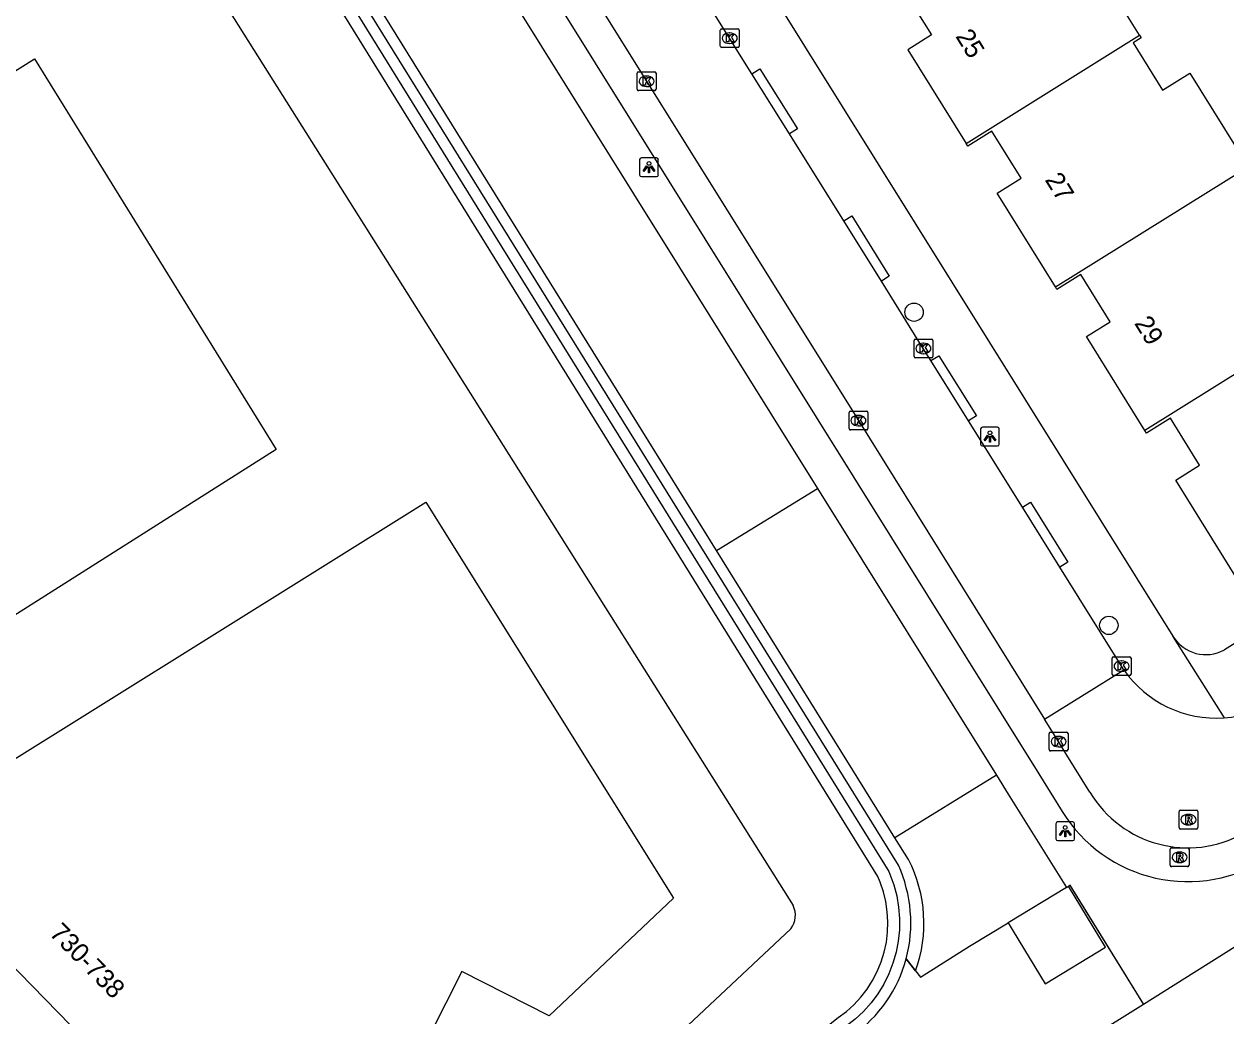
# Model space of a CAD drawing. Extents: x 158838 to 160074, y 386376 to 387776.
# Drawn here: x 159064.3 to 159128.3, y 386920.8 to 386973.6 of the extents above; entities that cross this region are included whole.
import ezdxf

# ---------------------------------------------------------------- set-up
doc = ezdxf.new("R2010")
doc.units = 0
for name, color, linetype in [('IMGEO_Boom', 7, 'Continuous'), ('IMGEO_Groenvoorziening', 7, 'Continuous'), ('IMGEO_Hek', 7, 'Continuous'), ('IMGEO_Kolk', 7, 'Continuous'), ('IMGEO_Lichtpunt', 7, 'Continuous'), ('IMGEO_Loofbos', 7, 'Continuous'), ('IMGEO_Muur', 7, 'Continuous'), ('IMGEO_Pand', 7, 'Continuous'), ('IMGEO_Pand_nummerreeks', 7, 'Continuous'), ('IMGEO_Rijbaan_lokaal_gesloten', 7, 'Continuous'), ('IMGEO_Rioolput', 7, 'Continuous'), ('IMGEO_Voetpad_open', 7, 'Continuous')]:
    doc.layers.add(name, color=color, linetype=linetype)

msp = doc.modelspace()

# ---------------------------------------------------------------- linework, layer by layer
at = {"layer": 'IMGEO_Boom'}
for centre in [(159111.716, 386958.243), (159122.083, 386941.572)]:
    msp.add_circle(centre, 0.489, dxfattribs=at)
at = {"layer": 'IMGEO_Groenvoorziening'}
for points in [[(159110.881, 386928.808), (159066.743, 387000), (159047.544, 387030.967)], [(159047.042, 387030.681), (159066.053, 387000), (159110.378, 386928.464), (159110.435, 386928.33), (159110.64, 386927.76), (159110.794, 386927.173), (159110.895, 386926.575), (159110.942, 386925.971), (159110.935, 386925.364), (159110.873, 386924.761), (159110.758, 386924.166), (159110.591, 386923.583), (159110.372, 386923.018), (159110.103, 386922.474), (159109.787, 386921.957), (159109.426, 386921.47), (159109.022, 386921.017), (159108.58, 386920.602), (159108.103, 386920.228), (159104.096, 386917.095), (159102.915, 386915.575)], [(159101.209, 386945.557), (159067.427, 387000), (159057.059, 387016.709)], [(159101.209, 386945.557), (159106.574, 386948.859)], [(159110.699, 386930.263), (159101.209, 386945.557)], [(159116.105, 386933.589), (159110.699, 386930.263)], [(159111.422, 386929.098), (159110.699, 386930.263)], [(159111.801, 386923.181), (159112.065, 386922.841), (159114.673, 386924.489), (159116.716, 386925.733)], [(159111.302, 386923.823), (159111.801, 386923.181)]]:
    msp.add_lwpolyline(points, dxfattribs=at)
for centre, radius, start, end in [((159104.809, 386925.704), 7.433, 340.1599, 27.16999), ((159104.003, 386925.717), 7.54, 345.4536, 24.20113), ((159104.188, 386925.752), 7.371, 305.33412, 344.82886)]:
    msp.add_arc(centre, radius, start, end, dxfattribs=at)
at = {"layer": 'IMGEO_Hek'}
msp.add_lwpolyline([(159111.801, 386923.181), (159111.302, 386923.823)], dxfattribs=at)
at = {"layer": 'IMGEO_Kolk'}
for p, q in [((159101.404, 386972.403), (159101.404, 386973.255)), ((159101.479, 386973.329), (159102.331, 386973.329)), ((159102.405, 386973.255), (159102.405, 386972.403)), ((159101.915, 386972.549), (159101.89, 386972.549)), ((159101.892, 386973.109), (159101.917, 386973.109)), ((159102.331, 386972.329), (159101.479, 386972.329)), ((159096.98, 386970.111), (159096.98, 386970.963)), ((159097.055, 386971.037), (159097.907, 386971.037)), ((159097.468, 386970.817), (159097.493, 386970.817)), ((159097.981, 386970.963), (159097.981, 386970.111)), ((159097.907, 386970.037), (159097.055, 386970.037)), ((159097.491, 386970.257), (159097.466, 386970.257)), ((159111.713, 386955.889), (159111.713, 386956.741)), ((159111.788, 386956.815), (159112.64, 386956.815)), ((159112.201, 386956.595), (159112.226, 386956.595)), ((159112.714, 386956.741), (159112.714, 386955.889)), ((159112.224, 386956.035), (159112.199, 386956.035)), ((159112.64, 386955.815), (159111.788, 386955.815)), ((159108.253, 386952.046), (159108.253, 386952.898)), ((159108.328, 386952.972), (159109.18, 386952.972)), ((159108.741, 386952.752), (159108.766, 386952.752)), ((159109.254, 386952.898), (159109.254, 386952.046)), ((159108.764, 386952.192), (159108.739, 386952.192)), ((159109.18, 386951.972), (159108.328, 386951.972)), ((159122.337, 386939.896), (159123.189, 386939.896)), ((159122.262, 386938.97), (159122.262, 386939.822)), ((159122.75, 386939.676), (159122.775, 386939.676)), ((159123.263, 386939.822), (159123.263, 386938.97)), ((159123.189, 386938.896), (159122.337, 386938.896)), ((159122.773, 386939.116), (159122.748, 386939.116)), ((159118.91, 386934.957), (159118.91, 386935.809)), ((159118.985, 386935.883), (159119.837, 386935.883)), ((159119.398, 386935.663), (159119.423, 386935.663)), ((159119.911, 386935.809), (159119.911, 386934.957)), ((159119.837, 386934.883), (159118.985, 386934.883)), ((159119.421, 386935.103), (159119.396, 386935.103))]:
    msp.add_line(p, q, dxfattribs=at)
for points in [[(159101.404, 386972.403), (159101.404, 386973.255)], [(159101.479, 386973.329), (159102.331, 386973.329)], [(159102.405, 386973.255), (159102.405, 386972.403)], [(159101.725, 386973.029), (159101.848, 386973.029), (159101.848, 386972.878), (159101.978, 386973.029), (159102.142, 386973.029), (159101.996, 386972.878), (159102.149, 386972.629), (159101.997, 386972.629), (159101.912, 386972.793), (159101.848, 386972.726), (159101.848, 386972.629), (159101.725, 386972.629), (159101.725, 386973.029)], [(159102.331, 386972.329), (159101.479, 386972.329)], [(159096.98, 386970.111), (159096.98, 386970.963)], [(159097.055, 386971.037), (159097.907, 386971.037)], [(159097.301, 386970.737), (159097.424, 386970.737), (159097.424, 386970.586), (159097.554, 386970.737), (159097.718, 386970.737), (159097.572, 386970.586), (159097.725, 386970.337), (159097.573, 386970.337), (159097.488, 386970.501), (159097.424, 386970.434), (159097.424, 386970.337), (159097.301, 386970.337), (159097.301, 386970.737)], [(159097.981, 386970.963), (159097.981, 386970.111)], [(159097.907, 386970.037), (159097.055, 386970.037)], [(159111.713, 386955.889), (159111.713, 386956.741)], [(159111.788, 386956.815), (159112.64, 386956.815)], [(159112.034, 386956.515), (159112.157, 386956.515), (159112.157, 386956.364), (159112.287, 386956.515), (159112.451, 386956.515), (159112.305, 386956.364), (159112.458, 386956.115), (159112.306, 386956.115), (159112.221, 386956.279), (159112.157, 386956.212), (159112.157, 386956.115), (159112.034, 386956.115), (159112.034, 386956.515)], [(159112.714, 386956.741), (159112.714, 386955.889)], [(159112.64, 386955.815), (159111.788, 386955.815)], [(159108.253, 386952.046), (159108.253, 386952.898)], [(159108.328, 386952.972), (159109.18, 386952.972)], [(159108.574, 386952.672), (159108.697, 386952.672), (159108.697, 386952.521), (159108.827, 386952.672), (159108.991, 386952.672), (159108.845, 386952.521), (159108.998, 386952.272), (159108.846, 386952.272), (159108.761, 386952.436), (159108.697, 386952.369), (159108.697, 386952.272), (159108.574, 386952.272), (159108.574, 386952.672)], [(159109.254, 386952.898), (159109.254, 386952.046)], [(159109.18, 386951.972), (159108.328, 386951.972)], [(159122.337, 386939.896), (159123.189, 386939.896)], [(159122.262, 386938.97), (159122.262, 386939.822)], [(159122.583, 386939.596), (159122.706, 386939.596), (159122.706, 386939.445), (159122.836, 386939.596), (159123, 386939.596), (159122.854, 386939.445), (159123.007, 386939.196), (159122.855, 386939.196), (159122.77, 386939.36), (159122.706, 386939.293), (159122.706, 386939.196), (159122.583, 386939.196), (159122.583, 386939.596)], [(159123.263, 386939.822), (159123.263, 386938.97)], [(159123.189, 386938.896), (159122.337, 386938.896)], [(159118.91, 386934.957), (159118.91, 386935.809)], [(159118.985, 386935.883), (159119.837, 386935.883)], [(159119.231, 386935.583), (159119.354, 386935.583), (159119.354, 386935.432), (159119.484, 386935.583), (159119.648, 386935.583), (159119.502, 386935.432), (159119.655, 386935.183), (159119.503, 386935.183), (159119.418, 386935.347), (159119.354, 386935.28), (159119.354, 386935.183), (159119.231, 386935.183), (159119.231, 386935.583)], [(159119.911, 386935.809), (159119.911, 386934.957)], [(159119.837, 386934.883), (159118.985, 386934.883)]]:
    msp.add_lwpolyline(points, dxfattribs=at)
for centre, start, end in [((159101.481, 386973.253), 91.55205, 178.44795), ((159101.481, 386973.253), 91.55205, 178.44795), ((159102.329, 386973.253), 1.55205, 88.44795), ((159102.329, 386973.253), 1.55205, 88.44795), ((159101.481, 386972.405), 181.55205, 268.44795), ((159101.481, 386972.405), 181.55205, 268.44795), ((159102.329, 386972.405), 271.55205, 358.44795), ((159102.329, 386972.405), 271.55205, 358.44795), ((159097.057, 386970.961), 91.55205, 178.44795), ((159097.057, 386970.961), 91.55205, 178.44795), ((159097.905, 386970.961), 1.55205, 88.44795), ((159097.905, 386970.961), 1.55205, 88.44795), ((159097.057, 386970.113), 181.55205, 268.44795), ((159097.057, 386970.113), 181.55205, 268.44795), ((159097.905, 386970.113), 271.55205, 358.44795), ((159097.905, 386970.113), 271.55205, 358.44795), ((159111.79, 386956.739), 91.55205, 178.44795), ((159111.79, 386956.739), 91.55205, 178.44795), ((159112.638, 386956.739), 1.55205, 88.44795), ((159112.638, 386956.739), 1.55205, 88.44795), ((159111.79, 386955.891), 181.55205, 268.44795), ((159111.79, 386955.891), 181.55205, 268.44795), ((159112.638, 386955.891), 271.55205, 358.44795), ((159112.638, 386955.891), 271.55205, 358.44795), ((159108.33, 386952.896), 91.55205, 178.44795), ((159108.33, 386952.896), 91.55205, 178.44795), ((159109.178, 386952.896), 1.55205, 88.44795), ((159109.178, 386952.896), 1.55205, 88.44795), ((159108.33, 386952.048), 181.55205, 268.44795), ((159108.33, 386952.048), 181.55205, 268.44795), ((159109.178, 386952.048), 271.55205, 358.44795), ((159109.178, 386952.048), 271.55205, 358.44795), ((159122.339, 386939.82), 91.55205, 178.44795), ((159122.339, 386939.82), 91.55205, 178.44795), ((159123.187, 386939.82), 1.55205, 88.44795), ((159123.187, 386939.82), 1.55205, 88.44795), ((159122.339, 386938.972), 181.55205, 268.44795), ((159122.339, 386938.972), 181.55205, 268.44795), ((159123.187, 386938.972), 271.55205, 358.44795), ((159123.187, 386938.972), 271.55205, 358.44795), ((159118.987, 386935.807), 91.55205, 178.44795), ((159118.987, 386935.807), 91.55205, 178.44795), ((159119.835, 386935.807), 1.55205, 88.44795), ((159119.835, 386935.807), 1.55205, 88.44795), ((159118.987, 386934.959), 181.55205, 268.44795), ((159118.987, 386934.959), 181.55205, 268.44795), ((159119.835, 386934.959), 271.55205, 358.44795), ((159119.835, 386934.959), 271.55205, 358.44795)]:
    msp.add_arc(centre, 0.0765, start, end, dxfattribs=at)
for centre, major_axis, ratio, start_param, end_param in [((159101.891, 386972.829), (-0.387, 0.002), 0.722429, 4.712389, 7.853982), ((159101.916, 386972.829), (-0.39, 0.002), 0.717154, 1.570796, 4.712389), ((159097.467, 386970.537), (-0.387, 0.002), 0.722429, 4.712389, 7.853982), ((159097.492, 386970.537), (-0.39, 0.002), 0.717154, 1.570796, 4.712389), ((159112.2, 386956.315), (-0.387, 0.002), 0.722429, 4.712389, 7.853982), ((159112.225, 386956.315), (-0.39, 0.002), 0.717154, 1.570796, 4.712389), ((159108.74, 386952.472), (-0.387, 0.002), 0.722429, 4.712389, 7.853982), ((159108.765, 386952.472), (-0.39, 0.002), 0.717154, 1.570796, 4.712389), ((159122.749, 386939.396), (-0.387, 0.002), 0.722429, 4.712389, 7.853982), ((159122.774, 386939.396), (-0.39, 0.002), 0.717154, 1.570796, 4.712389), ((159119.397, 386935.383), (-0.387, 0.002), 0.722429, 4.712389, 7.853982), ((159119.422, 386935.383), (-0.39, 0.002), 0.717154, 1.570796, 4.712389)]:
    msp.add_ellipse(centre, major_axis=major_axis, ratio=ratio, start_param=start_param, end_param=end_param, dxfattribs=at)
at = {"layer": 'IMGEO_Lichtpunt'}
for p, q in [((159097.108, 386966.365), (159097.108, 386965.558)), ((159097.108, 386966.365), (159097.108, 386965.558)), ((159098.01, 386966.46), (159097.202, 386966.46)), ((159098.01, 386966.46), (159097.202, 386966.46)), ((159098.104, 386965.558), (159098.104, 386966.365)), ((159098.104, 386965.558), (159098.104, 386966.365)), ((159097.202, 386965.464), (159098.01, 386965.464)), ((159097.202, 386965.464), (159098.01, 386965.464)), ((159115.257, 386952.026), (159115.257, 386951.219)), ((159115.257, 386952.026), (159115.257, 386951.219)), ((159116.159, 386952.121), (159115.351, 386952.121)), ((159116.159, 386952.121), (159115.351, 386952.121)), ((159116.253, 386951.219), (159116.253, 386952.026)), ((159116.253, 386951.219), (159116.253, 386952.026)), ((159115.351, 386951.125), (159116.159, 386951.125)), ((159115.351, 386951.125), (159116.159, 386951.125)), ((159119.265, 386931.011), (159119.265, 386930.204)), ((159119.265, 386931.011), (159119.265, 386930.204)), ((159120.167, 386931.106), (159119.359, 386931.106)), ((159120.167, 386931.106), (159119.359, 386931.106)), ((159120.261, 386930.204), (159120.261, 386931.011)), ((159120.261, 386930.204), (159120.261, 386931.011)), ((159119.359, 386930.11), (159120.167, 386930.11)), ((159119.359, 386930.11), (159120.167, 386930.11))]:
    msp.add_line(p, q, dxfattribs=at)
for points in [[(159097.482, 386966.029), (159097.521, 386966.001), (159097.333, 386965.739), (159097.295, 386965.766), (159097.482, 386966.029)], [(159097.584, 386965.981), (159097.631, 386965.981), (159097.631, 386965.659), (159097.584, 386965.659), (159097.584, 386965.981)], [(159097.694, 386966.001), (159097.732, 386966.028), (159097.919, 386965.766), (159097.88, 386965.738), (159097.694, 386966.001)], [(159115.631, 386951.69), (159115.67, 386951.662), (159115.482, 386951.4), (159115.444, 386951.427), (159115.631, 386951.69)], [(159115.733, 386951.642), (159115.78, 386951.642), (159115.78, 386951.32), (159115.733, 386951.32), (159115.733, 386951.642)], [(159115.843, 386951.662), (159115.881, 386951.689), (159116.068, 386951.427), (159116.029, 386951.399), (159115.843, 386951.662)], [(159119.639, 386930.675), (159119.678, 386930.647), (159119.49, 386930.385), (159119.452, 386930.412), (159119.639, 386930.675)], [(159119.741, 386930.627), (159119.788, 386930.627), (159119.788, 386930.305), (159119.741, 386930.305), (159119.741, 386930.627)], [(159119.851, 386930.647), (159119.889, 386930.674), (159120.076, 386930.412), (159120.037, 386930.384), (159119.851, 386930.647)]]:
    msp.add_lwpolyline(points, dxfattribs=at)
for centre in [(159097.607, 386966.163), (159115.756, 386951.824), (159119.764, 386930.809)]:
    msp.add_circle(centre, 0.0994, dxfattribs=at)
for centre, start, end in [((159097.202, 386966.365), 90, 180), ((159097.202, 386966.365), 90, 180), ((159098.01, 386966.365), 0, 90), ((159098.01, 386966.365), 0, 90), ((159097.202, 386965.558), 180, 270), ((159097.202, 386965.558), 180, 270), ((159098.01, 386965.558), 270, 0), ((159098.01, 386965.558), 270, 360), ((159115.351, 386952.026), 90, 180), ((159115.351, 386952.026), 90, 180), ((159116.159, 386952.026), 0, 90), ((159116.159, 386952.026), 0, 90), ((159115.351, 386951.219), 180, 270), ((159115.351, 386951.219), 180, 270), ((159116.159, 386951.219), 270, 0), ((159116.159, 386951.219), 270, 360), ((159119.359, 386931.011), 90, 180), ((159119.359, 386931.011), 90, 180), ((159120.167, 386931.011), 0, 90), ((159120.167, 386931.011), 0, 90), ((159119.359, 386930.204), 180, 270), ((159119.359, 386930.204), 180, 270), ((159120.167, 386930.204), 270, 0), ((159120.167, 386930.204), 270, 360)]:
    msp.add_arc(centre, 0.0946, start, end, dxfattribs=at)
at = {"layer": 'IMGEO_Loofbos'}
for points in [[(159102.365, 386915.829), (159103.677, 386917.524), (159107.676, 386920.687), (159108.111, 386921.014), (159108.514, 386921.378), (159108.884, 386921.777), (159109.216, 386922.207), (159109.509, 386922.665), (159109.759, 386923.147), (159109.966, 386923.65), (159110.127, 386924.17), (159110.24, 386924.701), (159110.306, 386925.241), (159110.323, 386925.784), (159110.292, 386926.327), (159110.212, 386926.865), (159110.085, 386927.393), (159109.911, 386927.908), (159109.791, 386928.194), (159065.319, 387000), (159046.571, 387030.271)], [(159027.668, 387025.411), (159031.623, 387024.617), (159033.066, 387024.328), (159037.285, 387026.957), (159040.771, 387029.129), (159042.317, 387026.665), (159042.882, 387025.766), (159059.05, 387000), (159105.278, 386926.65)], [(159105.16, 386925.412), (159097.39, 386918.123)]]:
    msp.add_lwpolyline(points, dxfattribs=at)
msp.add_arc((159104.205, 386926.128), 1.193, 323.14737, 25.96323, dxfattribs=at)
at = {"layer": 'IMGEO_Muur'}
msp.add_lwpolyline([(159119.995, 386927.764), (159123.926, 386921.395)], dxfattribs=at)
at = {"layer": 'IMGEO_Pand'}
for points in [[(159123.72, 386972.986), (159120.607, 386977.979), (159120.174, 386977.709), (159118.609, 386980.218), (159119.042, 386980.488), (159118.957, 386980.624)], [(159109.725, 386974.863), (159109.81, 386974.727), (159111.081, 386975.519), (159112.647, 386973.003), (159111.377, 386972.212), (159114.488, 386967.227)], [(159114.488, 386967.227), (159123.72, 386972.986)], [(159123.72, 386972.986), (159123.805, 386972.85), (159123.373, 386972.58), (159124.938, 386970.071), (159126.388, 386970.975), (159129.502, 386965.983)], [(159046.555, 386960.214), (159064.894, 386971.726), (159077.764, 386950.938), (159061.799, 386940.822), (159063.111, 386938.73), (159055.719, 386934.097), (159052.509, 386939.297)], [(159119.237, 386959.595), (159116.133, 386964.584), (159117.408, 386965.377), (159115.848, 386967.884), (159114.573, 386967.091), (159114.488, 386967.227)], [(159119.237, 386959.595), (159128.476, 386965.343), (159129.502, 386965.983)], [(159124.005, 386951.946), (159120.887, 386956.943), (159122.162, 386957.736), (159120.597, 386960.252), (159119.322, 386959.459), (159119.237, 386959.595)], [(159133.243, 386957.719), (159124.005, 386951.946)], [(159136.383, 386945.364), (159134.825, 386947.869), (159128.849, 386944.162), (159125.646, 386949.307), (159126.914, 386950.096), (159125.358, 386952.599), (159124.09, 386951.81), (159124.005, 386951.946)], [(159057.026, 386930.203), (159085.733, 386948.136), (159098.905, 386927.043), (159092.293, 386920.792), (159087.651, 386923.144), (159084.236, 386916.402), (159079.601, 386918.778), (159073.847, 386913.112), (159073.617, 386913.315), (159059.33, 386927.96), (159057.958, 386926.654), (159057.813, 386926.806), (159059.214, 386928.192), (159057.381, 386930.049), (159057.194, 386929.933)], [(159116.716, 386925.733), (159116.984, 386925.293), (159118.69, 386922.482), (159121.909, 386924.436), (159119.935, 386927.687)], [(159119.83, 386927.623), (159116.716, 386925.733)], [(159119.83, 386927.623), (159119.935, 386927.687)], [(159130.533, 386925.542), (159123.926, 386921.395)], [(159123.926, 386921.395), (159112.501, 386914.25), (159114.935, 386910.349), (159122.629, 386915.15), (159125.239, 386910.966)]]:
    msp.add_lwpolyline(points, dxfattribs=at)
at = {"layer": 'IMGEO_Rijbaan_lokaal_gesloten'}
for points in [[(159052.677, 387042.36), (159054.093, 387040.05), (159064.841, 387022.833), (159075.554, 387005.639), (159079.076, 387000), (159097.478, 386970.538), (159108.751, 386952.473), (159118.667, 386936.572)], [(159103.083, 386970.938), (159101.9, 386972.828), (159100.276, 386975.439)], [(159105.081, 386967.744), (159103.083, 386970.938)], [(159107.973, 386963.108), (159105.081, 386967.744)], [(159109.975, 386959.903), (159107.973, 386963.108)], [(159112.611, 386955.663), (159112.209, 386956.314), (159109.975, 386959.903)], [(159114.619, 386952.46), (159112.611, 386955.663)], [(159117.483, 386947.871), (159114.619, 386952.46)], [(159119.467, 386944.666), (159117.483, 386947.871)], [(159122.886, 386939.203), (159122.759, 386939.395), (159122.643, 386939.577), (159119.467, 386944.666)], [(159118.667, 386936.572), (159122.886, 386939.203)], [(159121.073, 386932.695), (159119.851, 386934.668), (159119.408, 386935.384), (159118.667, 386936.572)]]:
    msp.add_lwpolyline(points, dxfattribs=at)
for centre, radius, start, end in [((159127.81, 386942.629), 5.999, 214.82716, 273.88873), ((159127.814, 386942.619), 5.988, 273.86333, 303.44507), ((159126.285, 386935.792), 6.063, 210.71807, 299.47915)]:
    msp.add_arc(centre, radius, start, end, dxfattribs=at)
at = {"layer": 'IMGEO_Rioolput'}
for p, q in [((159125.821, 386930.803), (159125.821, 386931.655)), ((159125.896, 386931.729), (159126.748, 386931.729)), ((159126.822, 386931.655), (159126.822, 386930.803)), ((159126.332, 386930.949), (159126.307, 386930.949)), ((159126.309, 386931.509), (159126.334, 386931.509)), ((159126.748, 386930.729), (159125.896, 386930.729)), ((159125.35, 386928.799), (159125.35, 386929.651)), ((159125.425, 386929.725), (159126.277, 386929.725)), ((159126.351, 386929.651), (159126.351, 386928.799)), ((159125.838, 386929.505), (159125.863, 386929.505)), ((159126.277, 386928.725), (159125.425, 386928.725)), ((159125.861, 386928.945), (159125.836, 386928.945))]:
    msp.add_line(p, q, dxfattribs=at)
for points in [[(159125.821, 386930.803), (159125.821, 386931.655)], [(159125.896, 386931.729), (159126.748, 386931.729)], [(159126.822, 386931.655), (159126.822, 386930.803)], [(159126.41, 386931.427), (159126.158, 386931.429), (159126.158, 386931.029)], [(159126.158, 386931.029), (159126.282, 386931.029), (159126.282, 386931.191), (159126.293, 386931.191)], [(159126.336, 386931.348), (159126.282, 386931.348), (159126.282, 386931.267)], [(159126.282, 386931.267), (159126.334, 386931.267)], [(159126.34, 386931.162), (159126.411, 386931.029), (159126.551, 386931.029), (159126.486, 386931.155)], [(159126.748, 386930.729), (159125.896, 386930.729)], [(159125.35, 386928.799), (159125.35, 386929.651)], [(159125.425, 386929.725), (159126.277, 386929.725)], [(159126.351, 386929.651), (159126.351, 386928.799)], [(159125.939, 386929.423), (159125.687, 386929.425), (159125.687, 386929.025)], [(159125.687, 386929.025), (159125.811, 386929.025), (159125.811, 386929.187), (159125.822, 386929.187)], [(159125.865, 386929.344), (159125.811, 386929.344), (159125.811, 386929.263)], [(159125.811, 386929.263), (159125.863, 386929.263)], [(159125.869, 386929.158), (159125.94, 386929.025), (159126.08, 386929.025), (159126.015, 386929.151)], [(159126.277, 386928.725), (159125.425, 386928.725)]]:
    msp.add_lwpolyline(points, dxfattribs=at)
for centre, radius, start, end in [((159125.898, 386931.653), 0.0765, 91.55205, 178.44795), ((159125.898, 386931.653), 0.0765, 91.55205, 178.44795), ((159126.746, 386931.653), 0.0765, 1.55205, 88.44795), ((159126.746, 386931.653), 0.0765, 1.55205, 88.44795), ((159126.292, 386931.138), 0.0533, 26.02933, 88.69889), ((159126.318, 386931.456), 0.19, 274.7715, 282.96867), ((159126.342, 386931.252), 0.0964, 77.00612, 93.18647), ((159126.356, 386931.309), 0.0378, 276.66336, 79.67722), ((159126.409, 386931.317), 0.109, 350.36119, 89.41601), ((159126.407, 386931.317), 0.112, 277.58423, 350.98172), ((159126.391, 386931.102), 0.108, 29.51342, 73.79051), ((159125.898, 386930.805), 0.0765, 181.55205, 268.44795), ((159125.898, 386930.805), 0.0765, 181.55205, 268.44795), ((159126.746, 386930.805), 0.0765, 271.55205, 358.44795), ((159126.746, 386930.805), 0.0765, 271.55205, 358.44795), ((159125.427, 386929.649), 0.0765, 91.55205, 178.44795), ((159125.427, 386929.649), 0.0765, 91.55205, 178.44795), ((159126.275, 386929.649), 0.0765, 1.55205, 88.44795), ((159126.275, 386929.649), 0.0765, 1.55205, 88.44795), ((159125.821, 386929.134), 0.0533, 26.02933, 88.69889), ((159125.847, 386929.452), 0.19, 274.7715, 282.96867), ((159125.871, 386929.248), 0.0964, 77.00612, 93.18647), ((159125.885, 386929.305), 0.0378, 276.66336, 79.67722), ((159125.938, 386929.313), 0.109, 350.36119, 89.41601), ((159125.936, 386929.313), 0.112, 277.58423, 350.98172), ((159125.92, 386929.098), 0.108, 29.51342, 73.79051), ((159125.427, 386928.801), 0.0765, 181.55205, 268.44795), ((159125.427, 386928.801), 0.0765, 181.55205, 268.44795), ((159126.275, 386928.801), 0.0765, 271.55205, 358.44795), ((159126.275, 386928.801), 0.0765, 271.55205, 358.44795)]:
    msp.add_arc(centre, radius, start, end, dxfattribs=at)
for centre, major_axis, ratio, start_param, end_param in [((159126.308, 386931.229), (-0.387, 0.002), 0.722429, 4.712389, 7.853982), ((159126.333, 386931.229), (-0.39, 0.002), 0.717154, 1.570796, 4.712389), ((159125.837, 386929.225), (-0.387, 0.002), 0.722429, 4.712389, 7.853982), ((159125.862, 386929.225), (-0.39, 0.002), 0.717154, 1.570796, 4.712389)]:
    msp.add_ellipse(centre, major_axis=major_axis, ratio=ratio, start_param=start_param, end_param=end_param, dxfattribs=at)
at = {"layer": 'IMGEO_Voetpad_open'}
for points in [[(159069.441, 387030.819), (159076.524, 387019.468), (159125.496, 386940.988)], [(159074.653, 387000), (159106.574, 386948.859)], [(159076.971, 387000), (159118.351, 386933.666), (159119.599, 386931.666)], [(159103.083, 386970.938), (159103.505, 386971.202), (159105.504, 386968.009), (159105.081, 386967.744)], [(159107.973, 386963.108), (159108.397, 386963.372), (159110.399, 386960.167), (159109.975, 386959.903)], [(159112.611, 386955.663), (159113.034, 386955.928), (159115.042, 386952.725), (159114.619, 386952.46)], [(159106.574, 386948.859), (159116.105, 386933.589)], [(159117.483, 386947.871), (159117.908, 386948.134), (159119.892, 386944.929), (159119.467, 386944.666)], [(159136.383, 386945.364), (159128.234, 386940.266)], [(159125.496, 386940.988), (159125.509, 386940.94), (159128.217, 386936.644)], [(159116.105, 386933.589), (159116.732, 386932.585), (159119.83, 386927.623)], [(159119.935, 386927.687), (159120.013, 386927.734), (159123.926, 386921.395)]]:
    msp.add_lwpolyline(points, dxfattribs=at)
for centre, radius, start, end in [((159127.245, 386942.067), 2.055, 211.67238, 298.78281), ((159126.293, 386935.793), 7.864, 211.65715, 303.06551)]:
    msp.add_arc(centre, radius, start, end, dxfattribs=at)

# ---------------------------------------------------------------- texts
at = {"layer": 'IMGEO_Pand_nummerreeks'}
for s, rotation, p in [('25', 301.92141, (159113.896, 386972.93)), ('27', 301.92141, (159118.655, 386965.292)), ('29', 301.91927, (159123.413, 386957.654)), ('730-738', 314.51471, (159065.648, 386925.128))]:
    msp.add_text(s, height=1, rotation=rotation, dxfattribs=at).set_placement(p)

doc.saveas('drawing.dxf')
